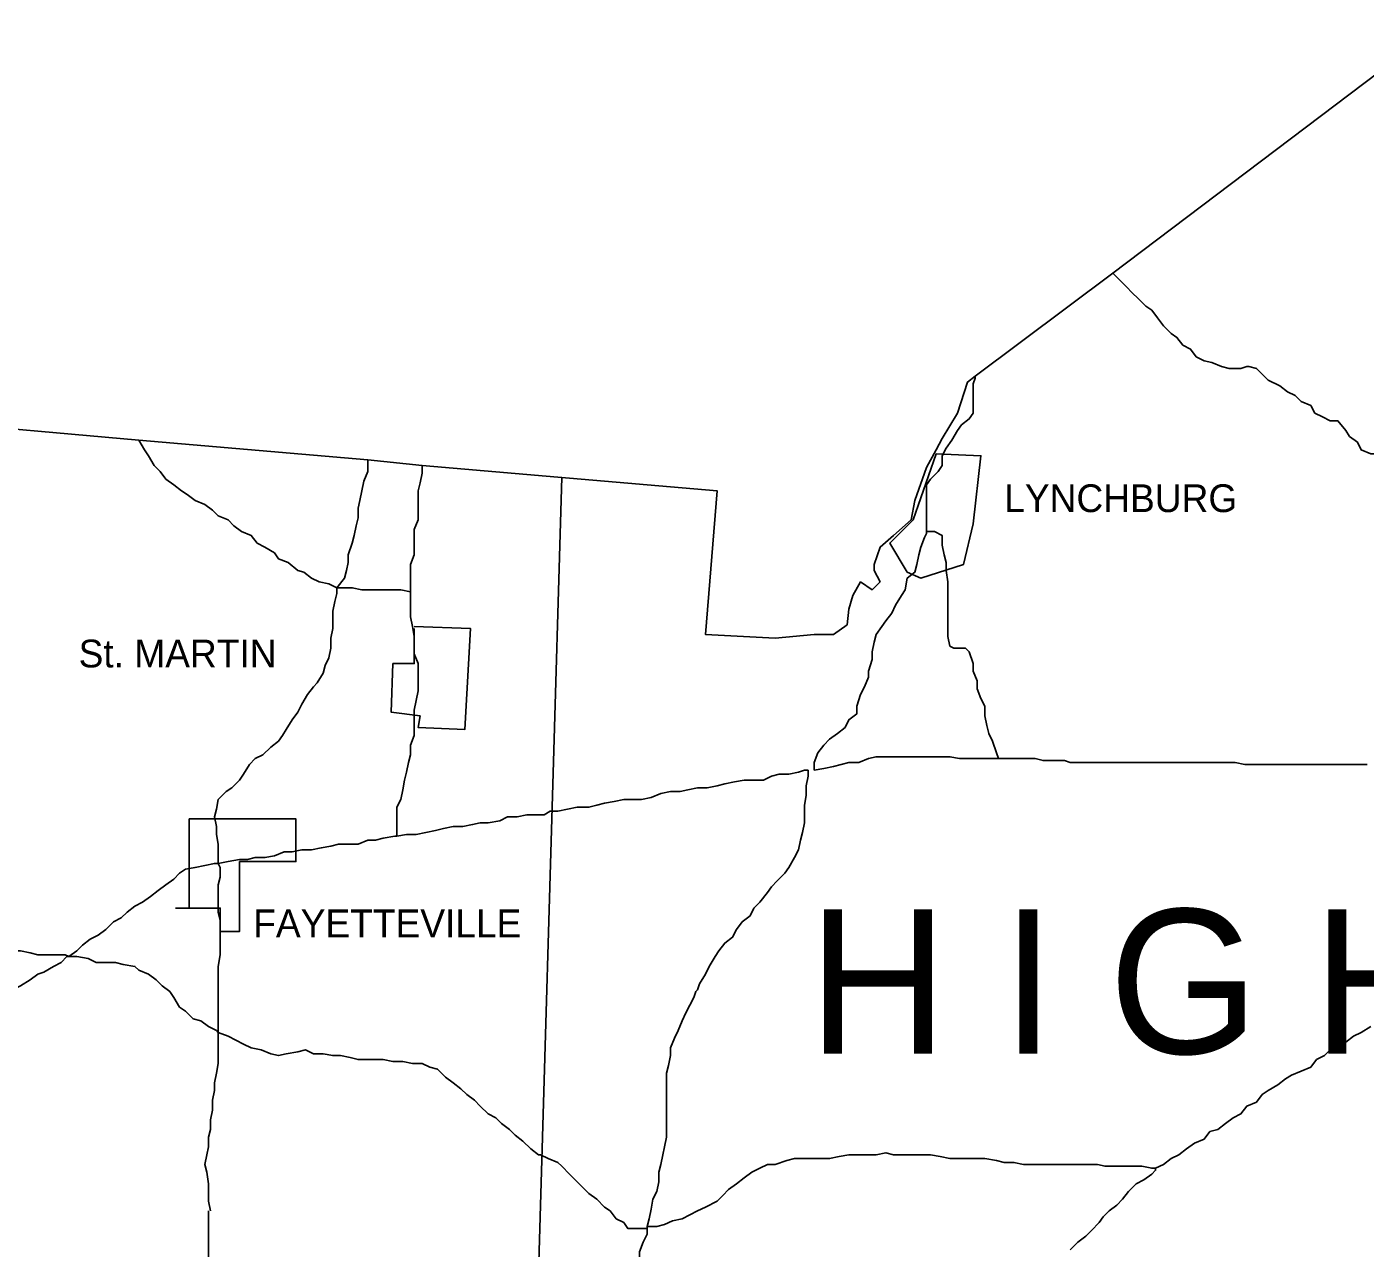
# Model space of a CAD drawing. Extents: x 0 to 40.2, y 0 to 22.
# Drawn here: x 2.608 to 3.548, y 18.216 to 19.074 of the extents above; entities that cross this region are included whole.
import ezdxf

# ---------------------------------------------------------------- set-up
doc = ezdxf.new("R2010")
doc.units = 0
doc.layers.add('Default', color=7, linetype='Continuous')
doc.layers.add('TR_Turning_Path1', color=7, linetype='Continuous')

msp = doc.modelspace()

# ---------------------------------------------------------------- linework, layer by layer
at = {"layer": 'Default'}
for points in [[(3.59972, 19.07403), (3.37066, 18.90087), (3.27386, 18.82861), (3.26841, 18.82452), (3.26159, 18.80271), (3.25068, 18.78498), (3.24659, 18.7768), (3.23977, 18.76453), (3.23159, 18.74135), (3.22887, 18.72772), (3.2166, 18.71681), (3.20705, 18.70863), (3.20296, 18.69636), (3.20296, 18.69227), (3.20705, 18.68409), (3.2016, 18.67864), (3.19342, 18.68409), (3.18796, 18.67455), (3.18524, 18.665), (3.18387, 18.6541), (3.17433, 18.64728), (3.1607, 18.64728), (3.13343, 18.64455), (3.08434, 18.64728), (3.09252, 18.74817), (2.98072, 18.75772)], [(3.37066, 18.90087), (3.37475, 18.89678), (3.38021, 18.89133), (3.3843, 18.88724), (3.38839, 18.88315), (3.39384, 18.8777), (3.39793, 18.87497), (3.40202, 18.86952), (3.40611, 18.86406), (3.41156, 18.85861), (3.41565, 18.85588), (3.41975, 18.85043), (3.4252, 18.8477), (3.42929, 18.84225), (3.43474, 18.83952), (3.4402, 18.83816), (3.44701, 18.83543), (3.45247, 18.83407), (3.46065, 18.83407), (3.46474, 18.83543), (3.4661, 18.83543)], [(3.23977, 18.71954), (3.23977, 18.72499), (3.23977, 18.73181), (3.23977, 18.73863), (3.23977, 18.74408), (3.23977, 18.75226), (3.2425, 18.75635), (3.24795, 18.76181), (3.25068, 18.7659), (3.25068, 18.77271), (3.25341, 18.77817), (3.2575, 18.78362), (3.26159, 18.79044), (3.26432, 18.79453), (3.26977, 18.79862), (3.2725, 18.80271), (3.2725, 18.80953), (3.2725, 18.81771), (3.2725, 18.82316), (3.27386, 18.82725), (3.27386, 18.82861)], [(3.4661, 18.83543), (3.47156, 18.83407), (3.47701, 18.82861), (3.47974, 18.82589), (3.48792, 18.8218), (3.49337, 18.81771), (3.49882, 18.81498), (3.50291, 18.81089), (3.50973, 18.80816), (3.51246, 18.80271), (3.51791, 18.79998), (3.52337, 18.79725), (3.52882, 18.79725), (3.53427, 18.79044), (3.537, 18.78635), (3.54245, 18.78226), (3.54518, 18.7768), (3.552, 18.77408), (3.55881, 18.77408), (3.56427, 18.77408), (3.56699, 18.77408), (3.56836, 18.77408)], [(2.98072, 18.75772), (2.88528, 18.7659), (2.84711, 18.76999), (2.68622, 18.78362), (2.53352, 18.79725)], [(2.68622, 18.78362), (2.69032, 18.7768), (2.69304, 18.77271), (2.69713, 18.7659), (2.70122, 18.76181), (2.70531, 18.75635), (2.71077, 18.75226), (2.71622, 18.74817), (2.72031, 18.74545), (2.72576, 18.74135), (2.73258, 18.73863), (2.73803, 18.73454), (2.74213, 18.73045), (2.74894, 18.72772), (2.75303, 18.72363), (2.75849, 18.71954), (2.7653, 18.71681), (2.76939, 18.71136), (2.77485, 18.70863), (2.78166, 18.70454), (2.78439, 18.70045), (2.79121, 18.69773), (2.79803, 18.69227), (2.80212, 18.69091), (2.80757, 18.68682), (2.81302, 18.68409), (2.81984, 18.68273), (2.82529, 18.68)], [(3.22614, 18.69091), (3.23568, 18.68682), (3.26568, 18.69636), (3.2725, 18.72499), (3.27795, 18.77271), (3.24659, 18.77408), (3.23023, 18.72772), (3.21387, 18.71136), (3.22614, 18.69091)], [(2.82529, 18.68), (2.83075, 18.68682), (2.83211, 18.69227), (2.83347, 18.69773), (2.83347, 18.70318), (2.8362, 18.71136), (2.83756, 18.71681), (2.83893, 18.72363), (2.84029, 18.72908), (2.84029, 18.7359), (2.84165, 18.74135), (2.84302, 18.74817), (2.84438, 18.75499), (2.84711, 18.76181), (2.84711, 18.76726), (2.84711, 18.76999)], [(2.8771, 18.67727), (2.8771, 18.68409), (2.8771, 18.68954), (2.8771, 18.69636), (2.87983, 18.70318), (2.87983, 18.70863), (2.87983, 18.71545), (2.87983, 18.7209), (2.88256, 18.72772), (2.88256, 18.73454), (2.88256, 18.74135), (2.88256, 18.74817), (2.88392, 18.75363), (2.88528, 18.76044), (2.88528, 18.7659), (2.88528, 18.7659)], [(2.98345, 18.75772), (2.963, 18.06237), (2.94527, 17.73515), (3.29158, 17.72561), (3.49337, 17.72697), (3.60517, 17.72288), (3.6488, 17.72152)], [(3.1607, 18.55184), (3.1607, 18.55729), (3.16342, 18.56411), (3.16751, 18.56956), (3.1716, 18.57365), (3.17706, 18.57774), (3.18251, 18.58183), (3.18524, 18.58729), (3.19069, 18.59138), (3.19069, 18.59683), (3.19342, 18.60501), (3.19614, 18.61047), (3.19887, 18.61728), (3.19887, 18.62137), (3.2016, 18.62955), (3.2016, 18.63501), (3.20296, 18.64183), (3.20432, 18.64728), (3.20841, 18.65273), (3.21114, 18.65682), (3.21523, 18.66228), (3.21796, 18.66773), (3.22205, 18.67455), (3.22478, 18.67864), (3.22614, 18.68682), (3.23159, 18.69091), (3.23296, 18.69636), (3.23432, 18.70318), (3.23568, 18.70863), (3.23841, 18.71545), (3.23977, 18.71818), (3.23977, 18.71954)], [(3.29022, 18.56002), (3.28886, 18.56411), (3.28613, 18.57229), (3.2834, 18.57774), (3.28204, 18.5832), (3.28068, 18.59002), (3.28068, 18.59683), (3.27795, 18.60229), (3.27522, 18.6091), (3.27522, 18.61456), (3.2725, 18.62137), (3.2725, 18.62683), (3.26977, 18.63501), (3.26704, 18.63773), (3.25886, 18.63773), (3.25613, 18.6391), (3.25477, 18.64592), (3.25477, 18.65273), (3.25477, 18.65955), (3.25477, 18.66637), (3.25477, 18.67182), (3.25477, 18.67864), (3.25477, 18.68409), (3.25341, 18.69227), (3.25341, 18.69773), (3.25204, 18.70318), (3.25068, 18.71), (3.25068, 18.71681), (3.24523, 18.71954), (3.24114, 18.71954), (3.23977, 18.71954)], [(2.74213, 18.4864), (2.74213, 18.49458), (2.74213, 18.50003), (2.74076, 18.50685), (2.74076, 18.5123), (2.7394, 18.51912), (2.74076, 18.52457), (2.74213, 18.53139), (2.74758, 18.53684), (2.75167, 18.53957), (2.75712, 18.54502), (2.75985, 18.54911), (2.76394, 18.55593), (2.76803, 18.56002), (2.77348, 18.56275), (2.77894, 18.5682), (2.78439, 18.57229), (2.78712, 18.57638), (2.78984, 18.58047), (2.79394, 18.58729), (2.79803, 18.59274), (2.80075, 18.5982), (2.80484, 18.60501), (2.80893, 18.61047), (2.81166, 18.61319), (2.81575, 18.62001), (2.81711, 18.62546), (2.81984, 18.63092), (2.8212, 18.63773), (2.8212, 18.64455), (2.82257, 18.65137), (2.82257, 18.65955), (2.82257, 18.66364), (2.82393, 18.67046), (2.82529, 18.67591), (2.82529, 18.68), (2.82529, 18.68)], [(2.82529, 18.68), (2.83075, 18.68), (2.8362, 18.68), (2.84302, 18.67864), (2.84984, 18.67864), (2.85665, 18.67864), (2.86347, 18.67864), (2.87029, 18.67864), (2.8771, 18.67727)], [(2.86756, 18.50548), (2.86756, 18.5123), (2.86756, 18.51912), (2.86756, 18.52593), (2.87029, 18.53139), (2.87165, 18.53821), (2.87301, 18.54502), (2.87438, 18.55048), (2.87574, 18.55729), (2.8771, 18.56275), (2.8771, 18.56956), (2.87983, 18.57638), (2.87983, 18.58183), (2.87983, 18.58865), (2.87983, 18.59411), (2.88119, 18.60092), (2.88256, 18.60774), (2.88256, 18.61319), (2.88256, 18.62137), (2.88256, 18.62683), (2.87983, 18.63364), (2.87983, 18.63773), (2.87983, 18.64592), (2.87847, 18.65273), (2.8771, 18.65955), (2.8771, 18.66637), (2.8771, 18.67046), (2.8771, 18.67727)], [(2.87983, 18.65273), (2.91937, 18.65137), (2.91528, 18.58047), (2.88256, 18.58183), (2.88392, 18.59002), (2.86347, 18.59274), (2.86483, 18.62683), (2.87983, 18.62683), (2.87983, 18.65137)], [(3.1607, 18.55184), (3.16751, 18.5532), (3.17433, 18.55457), (3.17978, 18.55593), (3.18524, 18.55729), (3.19205, 18.55729), (3.19887, 18.56002), (3.20432, 18.56138), (3.20978, 18.56138), (3.2166, 18.56138), (3.22341, 18.56138), (3.23023, 18.56138), (3.23568, 18.56138), (3.2425, 18.56138), (3.25068, 18.56138), (3.25613, 18.56138), (3.26295, 18.56002), (3.26841, 18.56002), (3.27522, 18.56002), (3.28068, 18.56002), (3.28749, 18.56002), (3.29022, 18.56002)], [(3.29022, 18.56002), (3.29704, 18.56002), (3.30249, 18.56002), (3.30931, 18.56002), (3.31613, 18.56002), (3.32158, 18.55866), (3.32976, 18.55866), (3.33658, 18.55866), (3.34067, 18.55729), (3.34885, 18.55729), (3.3543, 18.55729), (3.36248, 18.55729), (3.36794, 18.55729), (3.37339, 18.55729), (3.38157, 18.55729), (3.38702, 18.55729), (3.39384, 18.55729), (3.40066, 18.55729), (3.40611, 18.55729), (3.41293, 18.55729), (3.41975, 18.55729), (3.4252, 18.55729), (3.43202, 18.55729), (3.43883, 18.55729), (3.44701, 18.55729), (3.45247, 18.55729), (3.45656, 18.55729), (3.45656, 18.55729)], [(3.45656, 18.55729), (3.46337, 18.55593), (3.47156, 18.55593), (3.47837, 18.55593), (3.48519, 18.55593), (3.49064, 18.55593), (3.4961, 18.55593), (3.50291, 18.55593), (3.50973, 18.55593), (3.51791, 18.55593), (3.522, 18.55593), (3.52882, 18.55593), (3.53564, 18.55593), (3.54245, 18.55593), (3.54927, 18.55593)], [(2.97527, 18.52321), (2.98072, 18.52321), (2.98754, 18.52457), (2.99436, 18.52593), (3.00254, 18.52593), (3.00799, 18.5273), (3.01345, 18.52866), (3.02026, 18.53002), (3.02708, 18.53139), (3.0339, 18.53139), (3.03935, 18.53139), (3.04617, 18.53275), (3.05299, 18.53548), (3.0598, 18.53684), (3.06662, 18.53684), (3.07207, 18.53821), (3.07889, 18.53957), (3.08571, 18.53957), (3.09252, 18.54093), (3.09798, 18.5423), (3.1048, 18.54366), (3.11161, 18.54502), (3.11707, 18.54502), (3.12525, 18.54502), (3.1307, 18.54775), (3.13615, 18.54911), (3.14297, 18.54911), (3.14979, 18.55048), (3.15388, 18.55184), (3.15661, 18.55184)], [(3.07889, 18.39777), (3.08025, 18.40186), (3.08434, 18.40868), (3.08707, 18.41413), (3.09116, 18.42095), (3.09389, 18.42504), (3.09798, 18.43049), (3.10343, 18.43459), (3.10616, 18.44004), (3.11025, 18.44549), (3.1157, 18.44958), (3.11843, 18.45504), (3.12252, 18.45913), (3.12797, 18.46594), (3.1307, 18.47003), (3.13479, 18.47412), (3.14024, 18.47958), (3.14297, 18.48367), (3.14706, 18.49049), (3.14979, 18.49594), (3.15115, 18.50276), (3.15251, 18.50821), (3.15388, 18.51503), (3.15388, 18.52048), (3.15388, 18.5273), (3.15524, 18.53411), (3.15524, 18.54093), (3.15661, 18.54775), (3.15661, 18.55048), (3.15661, 18.55184)], [(2.71486, 18.45504), (2.74349, 18.45504), (2.74349, 18.43868), (2.75712, 18.43868), (2.75712, 18.48776), (2.79666, 18.48776), (2.79666, 18.51775), (2.72167, 18.51775), (2.72167, 18.45504), (2.71213, 18.45504)], [(2.86756, 18.50548), (2.87438, 18.50685), (2.88119, 18.50685), (2.88801, 18.50821), (2.89483, 18.50957), (2.90028, 18.51094), (2.9071, 18.5123), (2.91392, 18.5123), (2.92073, 18.51366), (2.92619, 18.51503), (2.93164, 18.51503), (2.93982, 18.51639), (2.94527, 18.51912), (2.95209, 18.51912), (2.95891, 18.52048), (2.96436, 18.52048), (2.97118, 18.52048), (2.97527, 18.52321)], [(2.74213, 18.4864), (2.74894, 18.48776), (2.75712, 18.48912), (2.76258, 18.48912), (2.76803, 18.49049), (2.77485, 18.49049), (2.78166, 18.49185), (2.78848, 18.49458), (2.79394, 18.49458), (2.80075, 18.49594), (2.80757, 18.49594), (2.81439, 18.4973), (2.8212, 18.49867), (2.82666, 18.50003), (2.83347, 18.50003), (2.84029, 18.50003), (2.84711, 18.50276), (2.85256, 18.50276), (2.85802, 18.50412), (2.8662, 18.50548), (2.86756, 18.50548)], [(2.63714, 18.42095), (2.6426, 18.42504), (2.64669, 18.42913), (2.65214, 18.43322), (2.65759, 18.43595), (2.66305, 18.44004), (2.6685, 18.44549), (2.67395, 18.44822), (2.67804, 18.45231), (2.6835, 18.4564), (2.68895, 18.45913), (2.69441, 18.46322), (2.69986, 18.46731), (2.70531, 18.4714), (2.71077, 18.47549), (2.71486, 18.47958), (2.71895, 18.4823), (2.72576, 18.48367), (2.73258, 18.48503), (2.7394, 18.4864), (2.74213, 18.4864)], [(2.74213, 18.36778), (2.74213, 18.37596), (2.74213, 18.38141), (2.74213, 18.38959), (2.74213, 18.39505), (2.74213, 18.40186), (2.74213, 18.40868), (2.74213, 18.41413), (2.74349, 18.42231), (2.74349, 18.42777), (2.74349, 18.43322), (2.74349, 18.44004), (2.74349, 18.44686), (2.74213, 18.45231), (2.74213, 18.45776), (2.74213, 18.46594), (2.74213, 18.4714), (2.74349, 18.47685), (2.74349, 18.48367), (2.74213, 18.4864)], [(2.50489, 18.43322), (2.51171, 18.43322), (2.51852, 18.43322), (2.52534, 18.43186), (2.53079, 18.43049), (2.53761, 18.43049), (2.54443, 18.42913), (2.55125, 18.42913), (2.5567, 18.42777), (2.56352, 18.42777), (2.57033, 18.4264), (2.57715, 18.4264), (2.5826, 18.42504), (2.58942, 18.42504), (2.59624, 18.42504), (2.60306, 18.42504), (2.60987, 18.42368), (2.61533, 18.42231), (2.62078, 18.42231), (2.62896, 18.42231), (2.63441, 18.42231), (2.63714, 18.42095)], [(2.5976, 18.39777), (2.60306, 18.4005), (2.60987, 18.40459), (2.61533, 18.40868), (2.61942, 18.41004), (2.62623, 18.41413), (2.63169, 18.41686), (2.63578, 18.42095), (2.63714, 18.42095)], [(2.63714, 18.42095), (2.6426, 18.42095), (2.65078, 18.41959), (2.65623, 18.41686), (2.66168, 18.41686), (2.66986, 18.41686), (2.67532, 18.4155), (2.6835, 18.41413), (2.68622, 18.41141), (2.69304, 18.40868), (2.6985, 18.40459), (2.70259, 18.4005), (2.70804, 18.39641), (2.71077, 18.39232), (2.71486, 18.3855), (2.71895, 18.38278), (2.7244, 18.37732), (2.72985, 18.37596), (2.73531, 18.37187), (2.74076, 18.36914), (2.74213, 18.36778)], [(3.04344, 18.23144), (3.0448, 18.23689), (3.04617, 18.24371), (3.04753, 18.25052), (3.05026, 18.25598), (3.05162, 18.26279), (3.05162, 18.26961), (3.05299, 18.27506), (3.05435, 18.28188), (3.05571, 18.28734), (3.05708, 18.29415), (3.05708, 18.29961), (3.05708, 18.30642), (3.05708, 18.31324), (3.05708, 18.31869), (3.05708, 18.32551), (3.05708, 18.33233), (3.05708, 18.33915), (3.05844, 18.3446), (3.0598, 18.35142), (3.0598, 18.35687), (3.06253, 18.36369), (3.06526, 18.36914), (3.06798, 18.37596), (3.07071, 18.38141), (3.07344, 18.38687), (3.07616, 18.39232), (3.07753, 18.39641), (3.07889, 18.39777)], [(2.73667, 18.24234), (2.73531, 18.24916), (2.73531, 18.25598), (2.73531, 18.26143), (2.73394, 18.26961), (2.73258, 18.27506), (2.73394, 18.28188), (2.73531, 18.28734), (2.73531, 18.29415), (2.73667, 18.29961), (2.73667, 18.30642), (2.73803, 18.31324), (2.73803, 18.32006), (2.7394, 18.32687), (2.7394, 18.33233), (2.74076, 18.33915), (2.74213, 18.34596), (2.74213, 18.35142), (2.74213, 18.35823), (2.74213, 18.36505), (2.74213, 18.36778)], [(2.74213, 18.36778), (2.74894, 18.36505), (2.7544, 18.36232), (2.75985, 18.3596), (2.7653, 18.35687), (2.77212, 18.35551), (2.77894, 18.35278), (2.78439, 18.35142), (2.78984, 18.35278), (2.79803, 18.35414), (2.80348, 18.35551), (2.80893, 18.35278), (2.81575, 18.35278), (2.82257, 18.35142), (2.82802, 18.35142), (2.83484, 18.35005), (2.84029, 18.34869), (2.84847, 18.34869), (2.85256, 18.34869), (2.85256, 18.34869)], [(3.40066, 18.27234), (3.40611, 18.27506), (3.41156, 18.27916), (3.41702, 18.28188), (3.42247, 18.28597), (3.42793, 18.29006), (3.43474, 18.29279), (3.43883, 18.29824), (3.44429, 18.29961), (3.44974, 18.3037), (3.45519, 18.30779), (3.46065, 18.31051), (3.46474, 18.31597), (3.47156, 18.31869), (3.47565, 18.32415), (3.47974, 18.32687), (3.48655, 18.33097), (3.49201, 18.33506), (3.4961, 18.33778), (3.50291, 18.34051), (3.50973, 18.34324), (3.51382, 18.34869), (3.51927, 18.35142), (3.52337, 18.35551), (3.52882, 18.35823), (3.53427, 18.36096), (3.53973, 18.36505), (3.54518, 18.36778), (3.552, 18.37187)], [(2.85256, 18.34869), (2.85802, 18.34869), (2.86483, 18.34733), (2.87165, 18.34733), (2.87847, 18.34596), (2.88528, 18.34596), (2.89074, 18.34324), (2.89619, 18.34187), (2.90165, 18.33642), (2.9071, 18.33233), (2.91255, 18.32824), (2.91664, 18.32415), (2.9221, 18.32006), (2.92619, 18.31597), (2.93164, 18.31051), (2.93709, 18.30779), (2.94118, 18.3037), (2.94664, 18.29961), (2.95073, 18.29552), (2.95618, 18.29143), (2.96164, 18.28597), (2.96709, 18.28188), (2.96845, 18.28188)], [(3.19887, 18.28188), (3.20432, 18.28188), (3.21114, 18.28325), (3.2166, 18.28188), (3.22341, 18.28188), (3.23023, 18.28188), (3.23568, 18.28188), (3.2425, 18.28188), (3.24932, 18.28052), (3.25613, 18.27916), (3.26295, 18.27916), (3.26841, 18.27916), (3.27522, 18.27916), (3.28068, 18.27916), (3.28886, 18.27779), (3.29431, 18.27643), (3.30113, 18.27643), (3.30794, 18.27506), (3.31476, 18.27506), (3.32158, 18.27506), (3.32703, 18.27506), (3.33249, 18.27506), (3.34067, 18.27506), (3.34612, 18.27506), (3.35294, 18.27506), (3.35975, 18.27506), (3.36521, 18.2737), (3.37339, 18.2737), (3.37884, 18.2737), (3.38702, 18.2737), (3.39111, 18.2737), (3.39793, 18.27234), (3.40066, 18.27234)], [(2.96845, 18.28188), (2.97391, 18.27916), (2.98072, 18.27643), (2.98345, 18.2737), (2.9889, 18.26825), (2.99436, 18.26279), (2.99845, 18.2587), (3.00254, 18.25461), (3.00799, 18.25052), (3.01345, 18.24507), (3.01754, 18.24234), (3.02163, 18.23689), (3.02708, 18.23416), (3.02981, 18.23007), (3.03662, 18.23007), (3.04344, 18.23007), (3.04344, 18.23144)], [(3.04344, 18.23144), (3.05026, 18.23144), (3.05571, 18.2328), (3.06117, 18.23553), (3.06798, 18.23689), (3.07344, 18.23962), (3.07889, 18.24234), (3.08434, 18.24507), (3.09252, 18.24916), (3.09661, 18.25325), (3.1007, 18.25734), (3.10616, 18.26143), (3.11161, 18.26552), (3.11707, 18.26961), (3.12252, 18.27234), (3.12797, 18.27506), (3.13343, 18.27506), (3.14161, 18.27779), (3.14706, 18.27916), (3.15251, 18.27916), (3.15933, 18.27916), (3.16615, 18.27916), (3.1716, 18.27916), (3.17842, 18.28052), (3.18524, 18.28188), (3.19069, 18.28188), (3.19751, 18.28188), (3.19887, 18.28188)], [(3.34067, 18.21507), (3.34612, 18.22053), (3.35157, 18.22462), (3.35566, 18.22871), (3.36112, 18.23416), (3.36384, 18.23825), (3.36794, 18.24234), (3.37339, 18.24643), (3.37748, 18.25052), (3.38157, 18.25598), (3.38702, 18.26143), (3.39248, 18.26416), (3.39793, 18.26825), (3.40066, 18.27097), (3.40066, 18.27234)], [(2.73803, 18.11827), (2.73803, 18.12509), (2.73803, 18.13191), (2.73803, 18.13872), (2.73667, 18.14418), (2.73667, 18.15099), (2.73667, 18.15781), (2.73667, 18.16326), (2.73667, 18.17144), (2.73531, 18.1769), (2.73531, 18.18235), (2.73531, 18.18917), (2.73531, 18.19599), (2.73531, 18.2028), (2.73531, 18.20826), (2.73531, 18.21507), (2.73531, 18.22189), (2.73531, 18.22871), (2.73531, 18.23553), (2.73531, 18.24234), (2.73531, 18.24234)], [(3.05299, 18.11418), (3.05162, 18.121), (3.05162, 18.12782), (3.05162, 18.13191), (3.05026, 18.13872), (3.04753, 18.14554), (3.04617, 18.15099), (3.04617, 18.15781), (3.0448, 18.16326), (3.04344, 18.17144), (3.04344, 18.1769), (3.04344, 18.18372), (3.04071, 18.18917), (3.03935, 18.19599), (3.03799, 18.20144), (3.03799, 18.20826), (3.03799, 18.21371), (3.04071, 18.22053), (3.04344, 18.22598), (3.04344, 18.23144)]]:
    msp.add_lwpolyline(points, dxfattribs=at)

# ---------------------------------------------------------------- texts
for s, height, p in [('LYNCHBURG', 0.019502, (3.29431, 18.73317)), ('St. MARTIN', 0.019502, (2.64396, 18.6241)), ('FAYETTEVILLE', 0.0195024, (2.76667, 18.43459))]:
    msp.add_text(s, height=height, dxfattribs=at).set_placement(p)
at = {"layer": 'TR_Turning_Path1'}
msp.add_text('H I G H L A N D', height=0.1014887, dxfattribs=at).set_placement((3.15661, 18.35278))

doc.saveas('drawing.dxf')
